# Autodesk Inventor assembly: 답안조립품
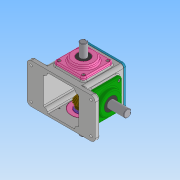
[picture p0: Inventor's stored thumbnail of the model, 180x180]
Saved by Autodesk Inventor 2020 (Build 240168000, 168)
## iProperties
Created: 2021-11
Part Number: 답안조립품
Document SubType Name: Assembly
Designer: user
Author: user
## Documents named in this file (16)
- C:\Users\user\Desktop\611112V1005\답안조립품.iam
- C:\Users\user\Desktop\611112V1005\메인커버.ipt
- C:\Users\user\Desktop\611112V1005\베어링 6203.ipt
- C:\Users\user\Desktop\611112V1005\베어링 6204.ipt
- C:\Users\user\Desktop\611112V1005\본체.ipt
- C:\Users\user\Desktop\611112V1005\볼트 M4.ipt
- C:\Users\user\Desktop\611112V1005\상부커버.ipt
- C:\Users\user\Desktop\611112V1005\서브베벨기어.ipt
- C:\Users\user\Desktop\611112V1005\서브축.ipt
- C:\Users\user\Desktop\611112V1005\서브커버.ipt
- C:\Users\user\Desktop\611112V1005\오일 실 17 32 8.ipt
- C:\Users\user\Desktop\611112V1005\오일 실 20 35 8.ipt
- C:\Users\user\Desktop\611112V1005\키 4x4.ipt
- C:\Users\user\Desktop\611112V1005\개스킷.ipt
- C:\Users\user\Desktop\611112V1005\메인베벨기어.ipt
- C:\Users\user\Desktop\611112V1005\메인축.ipt
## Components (1 placed, 1 different names)
1. 개스킷:1
